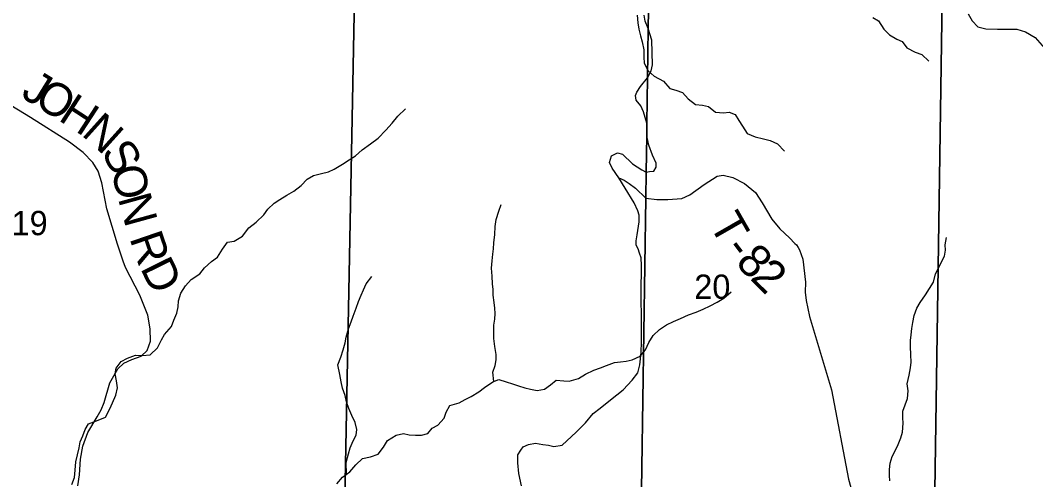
# Model space of a CAD drawing. Extents: x 2043100 to 2470832, y 443715 to 810583.
# Drawn here: x 2228187 to 2237420, y 618186 to 622361 of the extents above; entities that cross this region are included whole.
import ezdxf

# ---------------------------------------------------------------- set-up
doc = ezdxf.new("R2010")
doc.units = 0
for name, color, linetype in [('GM_X_Minor_River', 7, 'Continuous'), ('GM_X_Section', 7, 'Continuous'), ('GM_X_Section_Text', 7, 'Continuous'), ('GM_X_Township', 7, 'Continuous'), ('GM_X_Township_Road', 7, 'Continuous'), ('GM_X_Township_Road_Text', 7, 'Continuous'), ('GM_X_Township_ROW', 7, 'Continuous')]:
    doc.layers.add(name, color=color, linetype=linetype)

msp = doc.modelspace()

# ---------------------------------------------------------------- linework, layer by layer
at = {"layer": 'GM_X_Minor_River'}
for points in [[(2233796.6, 622406.8), (2233803.2, 622338.8), (2233811.7, 622280.8), (2233826.3, 622218.9), (2233842.7, 622167), (2233855.3, 622093), (2233857.9, 622025), (2233860.4, 621971), (2233897, 621901.2), (2233951.4, 621853.7), (2234035.7, 621808.3), (2234094.3, 621742.8), (2234146.4, 621725.2), (2234208.5, 621705.8), (2234259, 621648.2), (2234325.4, 621596.7), (2234389.4, 621589.2), (2234443.5, 621577.7), (2234509.9, 621526.2), (2234581.9, 621520.8), (2234633.8, 621527.3), (2234688, 621503.8), (2234720.4, 621450), (2234752.8, 621398.2), (2234797.4, 621332.5), (2234869.6, 621301.1), (2234943.7, 621283.8), (2235005.8, 621268.3), (2235072, 621238.8), (2235134.6, 621171.3)], [(2235939.3, 622385.4), (2235989.5, 622355.8), (2236040.1, 622280.2), (2236090.6, 622228.6), (2236156.9, 622189.2), (2236207, 622167.6), (2236249.5, 622111.9), (2236323.8, 622070.5), (2236385.9, 622049), (2236448.4, 621989.5)], [(2228653.9, 618142.2), (2228679.4, 618206.5), (2228686.8, 618272.6), (2228692.1, 618348.7), (2228707.5, 618410.9), (2228723, 618475.1), (2228732.5, 618529.3), (2228756, 618583.5), (2228777.4, 618641.8), (2228807, 618694.1), (2228880.7, 618720.7), (2228960.3, 618753.5), (2229001.6, 618829.9), (2229025.1, 618884.2), (2229056.5, 618954.5), (2229071.9, 619020.7), (2229061.3, 619084.7), (2229048.8, 619146.6), (2229058.3, 619198.8), (2229103.7, 619261.2), (2229161.4, 619291.8), (2229233.2, 619316.4), (2229297.1, 619314.9), (2229367, 619321.6), (2229434.4, 619384.2), (2229469.7, 619456.6), (2229497.3, 619506.9), (2229562.6, 619579.5), (2229584.1, 619635.7), (2229609.5, 619698), (2229621, 619756.2), (2229624.5, 619810.3), (2229647.8, 619882.5), (2229689.2, 619947), (2229740.7, 620005.5), (2229820.2, 620058.2), (2229861.7, 620112.6), (2229925.1, 620169.2), (2229980.7, 620209.7), (2230026, 620282.2), (2230071.5, 620344.7), (2230131.3, 620355.2), (2230206.9, 620399.9), (2230264.2, 620474.4), (2230331.7, 620527.1), (2230401, 620593.7), (2230438.6, 620644.1), (2230494, 620700.6), (2230545.7, 620733.1), (2230609.3, 620771.7), (2230674.9, 620808.3), (2230740.4, 620860.9), (2230795.9, 620917.5), (2230851.6, 620950), (2230925.3, 620968.6), (2230989.2, 620983.2), (2231040.9, 621007.7), (2231116.5, 621052.3), (2231178.1, 621092.9), (2231233.7, 621129.4), (2231295.2, 621184), (2231372.6, 621238.7), (2231440.1, 621291.4), (2231511.5, 621362.1), (2231568.8, 621426.6), (2231618.3, 621489.1), (2231689.6, 621555.8)], [(2232492.5, 619079.9), (2232484.2, 619162.3), (2232503.6, 619222.6), (2232515.2, 619274.7), (2232514.7, 619324.8), (2232502.1, 619396.7), (2232493.5, 619468.7), (2232492.4, 619590.8), (2232501.9, 619645), (2232503.5, 619695), (2232501, 619745.1), (2232494.6, 619797.1), (2232488, 619863.1), (2232485.6, 619913.1), (2232481.1, 619967.1), (2232476.5, 620035.2), (2232471.8, 620107.2), (2232477.2, 620175.3), (2232484.7, 620235.4), (2232488.3, 620285.5), (2232491.8, 620339.6), (2232501.1, 620415.7), (2232504.5, 620485.8), (2232513.9, 620550), (2232537.2, 620626.2), (2232558.7, 620688.5)], [(2236092.3, 618174.6), (2236089.9, 618224.6), (2236089.4, 618278.7), (2236096.9, 618334.8), (2236116.3, 618397), (2236141.9, 618447.3), (2236169.3, 618505.6), (2236192.8, 618567.9), (2236210.3, 618618.1), (2236215.6, 618698.2), (2236213.2, 618748.2), (2236212.6, 618808.3), (2236232.1, 618866.5), (2236253.6, 618922.8), (2236259, 618994.9), (2236252.4, 619056.9), (2236269.7, 619135.1), (2236283.1, 619203.3), (2236286.7, 619253.4), (2236286.1, 619321.5), (2236281.4, 619395.5), (2236282.9, 619449.6), (2236286.5, 619503.7), (2236294, 619559.8), (2236301.5, 619613.9), (2236314.9, 619678.1), (2236340.3, 619744.4), (2236369.8, 619796.7), (2236419.2, 619865.2), (2236490.1, 619981.9), (2236509.4, 620056.2), (2236591.9, 620217), (2236599.5, 620271.2), (2236597, 620321.2), (2236610.4, 620387.4)], [(2231153.1, 618236.5), (2231150.4, 618341.9), (2231169.7, 618422.2), (2231187.2, 618474.4), (2231214.6, 618538.7), (2231240.1, 618591), (2231247.7, 618643.1), (2231231.1, 618705), (2231200.6, 618768.8), (2231174, 618832.7), (2231153.5, 618894.5), (2231141, 618950.5), (2231116.4, 619018.4), (2231106, 619074.3), (2231093.4, 619142.3), (2231074.6, 619230.2), (2231102, 619298.5), (2231123.3, 619366.8), (2231140.8, 619431), (2231150.3, 619481.1), (2231171.6, 619557.4), (2231195, 619621.7), (2231214.6, 619671.9), (2231241.9, 619744.2), (2231263.4, 619806.4), (2231284.9, 619862.7), (2231306.4, 619912.9), (2231331.9, 619967.2), (2231383.3, 620031.7)], [(2234125, 619623), (2234190.7, 619649.6), (2234262.3, 619684.3), (2234332, 619708.9), (2234395.8, 619735.5), (2234461.4, 619766.1), (2234523.1, 619798.7), (2234584.7, 619837.2), (2234652.2, 619891.9)], [(2231064.2, 618149), (2231115.6, 618209.5), (2231183.1, 618258.1), (2231236.5, 618320.7), (2231298, 618379.3), (2231369.8, 618393.9), (2231439.5, 618416.5), (2231488.9, 618481), (2231526.3, 618543.4), (2231603.9, 618590.1), (2231671.7, 618604.7), (2231723.8, 618593.2), (2231781.7, 618589.7), (2231833.7, 618590.1), (2231891.5, 618604.6), (2231933.1, 618655), (2231984.8, 618681.5), (2232042.2, 618746.1), (2232059.7, 618798.3), (2232093.1, 618860.6), (2232178.8, 618885.4), (2232232.5, 618915.9), (2232286.3, 618942.4), (2232355.8, 618985), (2232407.5, 619023.5), (2232482.9, 619076.2), (2232536.7, 619096.7), (2232604.9, 619075.3), (2232661, 619057.8), (2232717.1, 619040.2), (2232775.2, 619020.7), (2232825.3, 619009.1), (2232885.4, 618997.6), (2232953.2, 619010.2), (2233008.8, 619046.8), (2233060.4, 619089.2), (2233128.4, 619085.8), (2233178.4, 619080.3), (2233264.1, 619105), (2233327.7, 619145.6), (2233403.4, 619180.3), (2233463.1, 619202.9), (2233516.9, 619225.3), (2233590.6, 619252), (2233644.5, 619256.5), (2233696.4, 619262.9), (2233750.3, 619275.4), (2233823.9, 619308.1), (2233871.4, 619366.6), (2233900.8, 619432.9), (2233942.2, 619495.3), (2233999.7, 619549.9), (2234063.3, 619592.5), (2234125, 619623)]]:
    msp.add_lwpolyline(points, dxfattribs=at)
at = {"layer": 'GM_X_Section'}
for points in [[(2225999.9, 623146.3), (2231234.9, 623048.7), (2231137.2, 618011.7), (2225917.9, 618135.5)], [(2231234.9, 623048.7), (2236575.8, 622964.2), (2236500.6, 617881.4), (2231137.2, 618011.7)], [(2236575.8, 622964.2), (2241920.7, 622885.8), (2241833.9, 617758.8), (2236500.6, 617881.4)]]:
    msp.add_lwpolyline(points, close=True, dxfattribs=at)
at = {"layer": 'GM_X_Township'}
for points in [[(2258081.3, 633732.5), (2257992.6, 628603.2), (2257760.5, 615186.1), (2257653.2, 607589.5), (2257624.6, 606994.4), (2257596.4, 606358.1), (2253890.2, 606463.4), (2249021.7, 606637.8), (2248304.7, 606663.3), (2243521.3, 606786.8), (2239722.4, 606909.9), (2234400.7, 607082.4), (2233675.1, 607105.9), (2233758.1, 612789.2), (2233874.4, 620743.5), (2233877.9, 620982.4), (2233882.7, 621311.5), (2233884.4, 621427.4), (2233890.3, 621836.9), (2233896.9, 622286.3), (2233904.3, 622790.6), (2233907.5, 623014), (2234072.5, 630720.1), (2234171.5, 633589.1)], [(2234171.5, 633589.1), (2234072.5, 630720.1), (2233907.5, 623014), (2233904.3, 622790.6), (2233896.9, 622286.3), (2233890.3, 621836.9), (2233884.4, 621427.4), (2233882.7, 621311.5), (2233877.9, 620982.4), (2233874.4, 620743.5), (2233758.1, 612789.2), (2233675.1, 607105.9), (2232181.4, 607137.8), (2228778, 607244.9), (2226312.1, 607230.9), (2225669.9, 607239), (2225670.8, 607315.3), (2224362.8, 607365.3), (2223684.1, 607391.3), (2220321.1, 607518.2)]]:
    msp.add_lwpolyline(points, dxfattribs=at)
at = {"layer": 'GM_X_Township_Road'}
for points in [[(2236806.3, 622419.2), (2236842.9, 622355.4), (2236895.4, 622301.8), (2236965.6, 622284.4), (2237073.7, 622281.4), (2237247.9, 622281), (2237326.1, 622257.6), (2237416.7, 622204.3), (2237501.6, 622106.9)], [(2232743.5, 618129.9), (2232721.4, 618243.7), (2232712.5, 618339.8), (2232711.8, 618410.7), (2232737.2, 618453.2), (2232758.9, 618484.5), (2232807.6, 618504.4), (2232870.5, 618516.6), (2232939, 618506.6), (2232988.7, 618501.1), (2233039.6, 618488.9), (2233114.8, 618498.8), (2233240.6, 618618.2), (2233325.7, 618703.3), (2233396.9, 618787.4), (2233458.3, 618836.4), (2233553.3, 618911.9), (2233670.1, 619003.8), (2233750.9, 619091.1), (2233801.8, 619156.2), (2233821.7, 619231.3), (2233831.7, 619341.8), (2233836.1, 619440.1), (2233835, 619615.8), (2233833.9, 619880.9), (2233835, 620133.9), (2233832.8, 620201.3), (2233817.3, 620244.4), (2233804, 620284.2), (2233787.5, 620318), (2233786.9, 620356.1), (2233796.2, 620410.3), (2233814.5, 620530.8), (2233815.6, 620588.9), (2233801, 620630.8), (2233767.9, 620701.6), (2233687.4, 620836.8), (2233629.5, 620928.5), (2233568.4, 621017), (2233545.8, 621070.1), (2233561.7, 621130.2), (2233618.2, 621155.4), (2233661.7, 621143.3), (2233753.4, 621056.5), (2233837.1, 621001.7), (2233877.9, 620982.4), (2233907.1, 620985.6), (2233948.9, 620991.3), (2233969, 621025.1), (2233967.4, 621062.1), (2233936.1, 621135.3), (2233901.5, 621226.2), (2233882.7, 621311.5), (2233884.4, 621427.4), (2233853.2, 621528.7), (2233830.7, 621583.5), (2233787.2, 621636.6), (2233782.9, 621657.7), (2233781.8, 621676.9), (2233792.5, 621706.7), (2233827.7, 621759), (2233890.3, 621836.9), (2233924.8, 621901), (2233935.5, 621955.4), (2233930.2, 622181.6), (2233896.9, 622286.3), (2233869.6, 622354.1), (2233858.7, 622407.2)], [(2228708.7, 618130.2), (2228725.3, 618228.6), (2228733.3, 618371), (2228755.6, 618491.6), (2228799.9, 618614.5), (2228885.9, 618756), (2228921.1, 618820.6), (2228948.1, 618887.1), (2229001.6, 619066.3), (2229073.9, 619193.5), (2229129.2, 619244.4), (2229200.8, 619277.5), (2229284.4, 619308.8), (2229339.7, 619359.7), (2229370.5, 619446.3), (2229368.9, 619558.5), (2229345.1, 619680.4), (2229272.5, 619861.7), (2229142.8, 620114.3), (2229122, 620172.1), (2229071.8, 620325.6), (2228975.1, 620648.8), (2228927.7, 620884.6), (2228896.2, 620990.3), (2228847, 621069.8), (2228759.7, 621158.7), (2228634.2, 621255), (2228280.8, 621478.3), (2228046.6, 621621.2)], [(2233629.5, 620928.5), (2233677.8, 620907.6), (2233723.4, 620878.1), (2233782.4, 620836.8), (2233874.4, 620743.5), (2233973.9, 620733.8), (2234075.8, 620732.9), (2234200.8, 620741.9), (2234276.4, 620774), (2234406.7, 620867.4), (2234523.1, 620945.8), (2234579, 620954.7), (2234667.4, 620933.9), (2234772.2, 620879.3), (2234871.5, 620796.6), (2234932.9, 620701.3), (2235021, 620554.4), (2235092.3, 620467.2), (2235181.6, 620384.4), (2235230.7, 620333.6)]]:
    msp.add_lwpolyline(points, dxfattribs=at)
at = {"layer": 'GM_X_Township_ROW'}
msp.add_lwpolyline([(2235230.7, 620333.6), (2235244.5, 620319.2), (2235258.9, 620297.3), (2235273.2, 620275.5), (2235302.4, 620189.8), (2235327.4, 619981.7), (2235324.7, 619891.5), (2235333.8, 619813.5), (2235363.9, 619667.7), (2235563.5, 619001.3), (2235719.1, 618192), (2235955.4, 617341.7)], dxfattribs=at)

# ---------------------------------------------------------------- texts
at = {"layer": 'GM_X_Section_Text'}
for s, p in [('19', (2228107, 620408.2)), ('20', (2234315.4, 619829.6))]:
    msp.add_text(s, height=220.83, rotation=0.00001, dxfattribs=at).set_placement(p)
at = {"layer": 'GM_X_Township_Road_Text'}
for s, rotation, p in [('J', 328.34865, (2228181, 621670.6)), ('O', 328.22282, (2228300.7, 621596.8)), ('H', 326.93735, (2228523.6, 621458.7)), ('N', 317.99952, (2228735, 621322.2)), ('S', 300.14563, (2228915.7, 621164.7)), ('O', 283.53442, (2229008.9, 621010.9)), ('N', 285.3922, (2229073.3, 620743.9)), ('T', 299.85386, (2234445.8, 620508.2)), ('R', 288.98219, (2229177.2, 620381.7)), ('-', 307.22666, (2234580.8, 620278.6)), ('8', 314.04129, (2234680.6, 620151)), ('D', 296.28675, (2229273.4, 620110.1)), ('2', 315.3974, (2234814.6, 620012.6))]:
    msp.add_text(s, height=300, rotation=rotation, dxfattribs=at).set_placement(p)

doc.saveas('drawing.dxf')
